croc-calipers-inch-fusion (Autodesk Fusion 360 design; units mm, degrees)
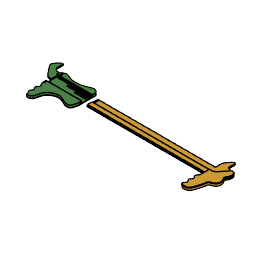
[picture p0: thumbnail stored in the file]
named bodies: "rule_main_body", "eye1_wt", "eye2_wt", "eye1center_blk", "eye2center_blk", "freckle1_blk", "freckle2_blk", "freckle3_blk", "freckle4_blk", "freckle5_blk", "eyebrow1_blk", "freckle6_blk", "eyebrow2_blk", "slide_body", "slide_ticmark_btm", "slide_ticmark_top", "text_5_blk", "text_2_blk", "text_4_blk", "text_8_blk", "text_7_blk", "text_0_blk", "text_1_blk", "text_6_blk", "text_3_blk", "scale_btm_blk", "scale_top_blk"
